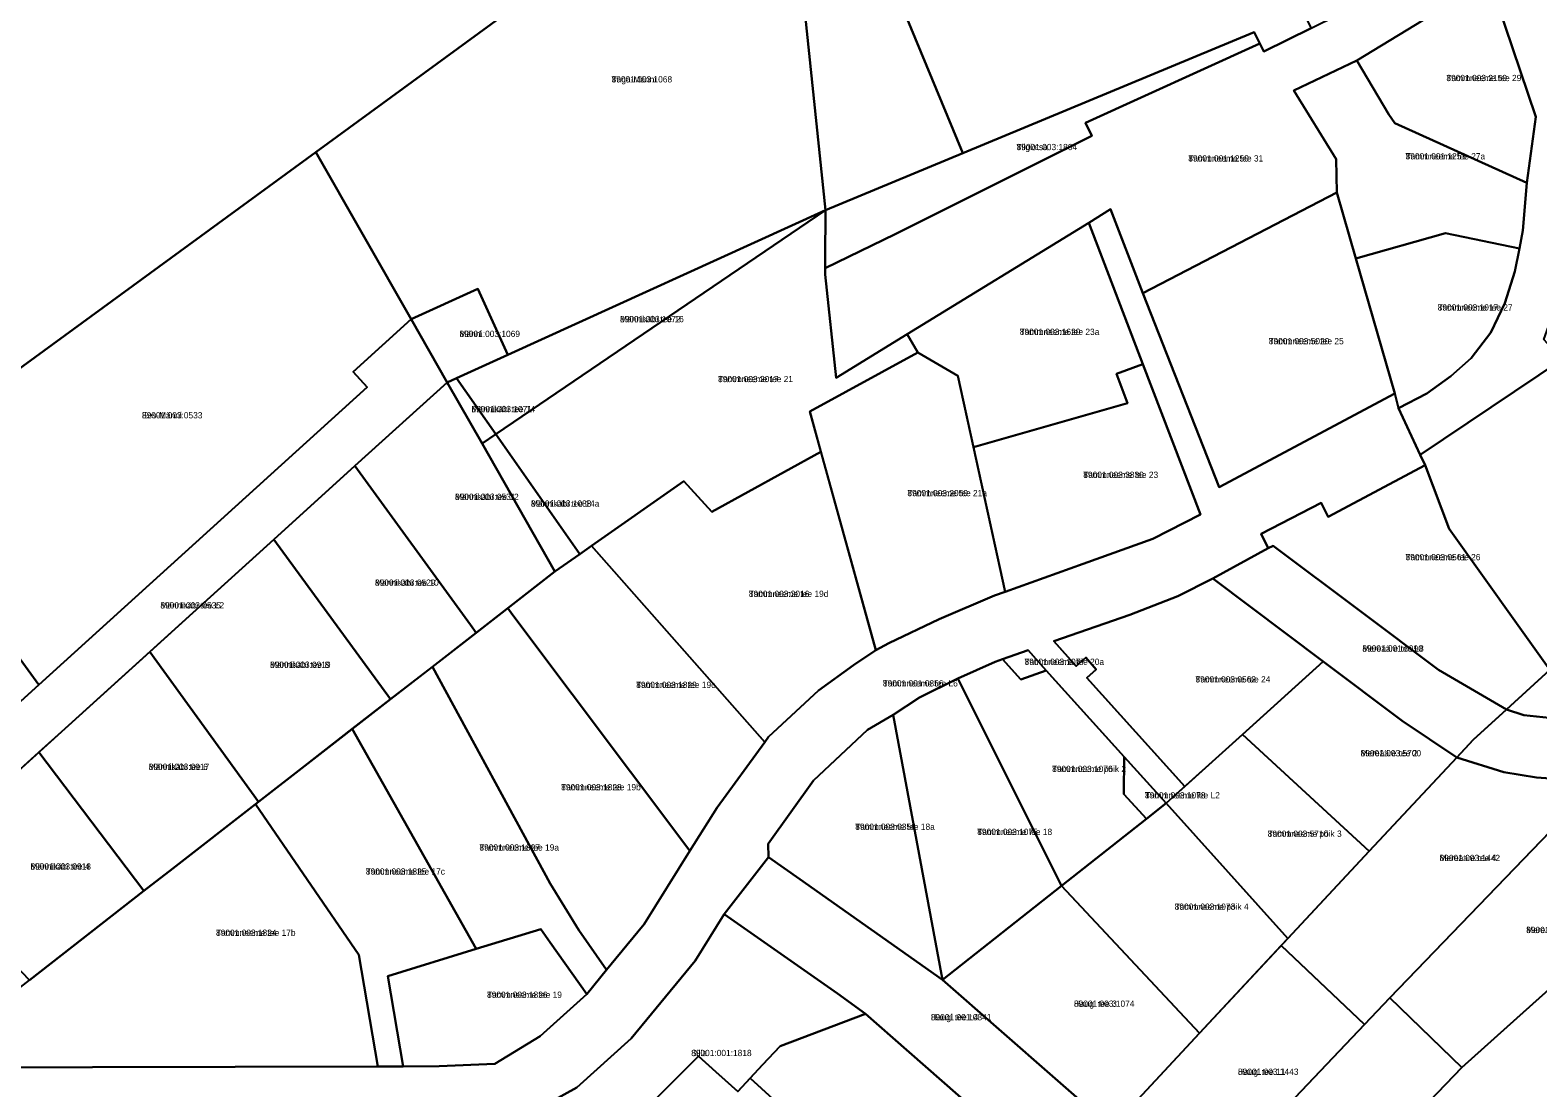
# Model space of a CAD drawing. Extents: x 526849 to 562296, y 6591741 to 6618546.
# Drawn here: x 549963.2 to 550324.5, y 6599418.5 to 6599671.9 of the extents above; entities that cross this region are included whole.
import ezdxf

# ---------------------------------------------------------------- set-up
doc = ezdxf.new("R2010")
doc.units = 0
for name, color, linetype in [('L_AADRESS', 7, 'Continuous'), ('PIIR', 7, 'Continuous'), ('TUNNUS', 7, 'Continuous')]:
    doc.layers.add(name, color=color, linetype=linetype)

msp = doc.modelspace()

# ---------------------------------------------------------------- linework, layer by layer
at = {"layer": 'PIIR'}
for points in [[(550120.44, 6599951.5), (550131.86, 6599957.71), (550132.14, 6599955.03), (550135.52, 6599922.21), (550142.38, 6599855.54), (550143.2, 6599847.59), (550143.81, 6599841.62), (550148.68, 6599794.24), (550154.07, 6599741.82), (550160.25, 6599682.56), (550224.97, 6599706.61), (550249.04, 6599715.69), (550253.16, 6599705.99), (550173, 6599675.56), (550186.76, 6599642.4), (550153.82, 6599628.72), (550143.83, 6599724.58), (550134.04, 6599819.27)], [(550031.61, 6599642.67), (549950.11, 6599583.16), (549916.41, 6599620.77), (549895.32, 6599597.71), (549870.31, 6599624.72), (549877.15, 6599630.15), (549878.36, 6599631.04), (549903.73, 6599650.97), (549961.17, 6599692.9), (549996.94, 6599718.81), (550000, 6599721.04), (550069, 6599771.36), (550116.4, 6599805.93), (550119.7, 6599808.82), (550124.58, 6599812.65), (550134.04, 6599819.27), (550143.83, 6599724.58)], [(550031.61, 6599642.67), (550143.83, 6599724.58), (550153.82, 6599628.72), (550077.68, 6599594.11), (550070.5, 6599609.89), (550054.48, 6599602.6)], [(550186.76, 6599642.4), (550173, 6599675.56), (550253.16, 6599705.99), (550268.85, 6599674.99), (550270.2, 6599672.33), (550258.83, 6599666.72), (550257.88, 6599668.71), (550256.55, 6599671.4)], [(550153.69, 6599613.3), (550153.7, 6599614.84), (550170.52, 6599622.98), (550217.62, 6599646.57), (550216.15, 6599649.66), (550257.88, 6599668.71), (550258.83, 6599666.72), (550270.2, 6599672.33), (550310.36, 6599692.2), (550311.12, 6599689.81), (550312.95, 6599684.03), (550281.15, 6599664.63), (550266.03, 6599657.45), (550276.22, 6599640.99), (550276.37, 6599633), (550229.88, 6599608.87), (550222.15, 6599628.97), (550216.9, 6599625.73), (550173.42, 6599599.06), (550156.38, 6599588.61)], [(550312.95, 6599684.03), (550324.05, 6599651.14), (550321.94, 6599635.28), (550290.28, 6599649.56), (550288.79, 6599651.69), (550281.15, 6599664.63)], [(550153.82, 6599628.72), (550186.76, 6599642.4), (550256.55, 6599671.4), (550257.88, 6599668.71), (550216.15, 6599649.66), (550217.62, 6599646.57), (550170.52, 6599622.98), (550153.7, 6599614.84), (550153.73, 6599616.85)], [(550381.16, 6599658.31), (550390.31, 6599664.95), (550393.25, 6599655.51), (550398.33, 6599645.98), (550405.31, 6599634.63), (550407.66, 6599631.74), (550410.09, 6599627.45), (550417.22, 6599616.57), (550420.09, 6599612.89), (550411.05, 6599603.17), (550379.65, 6599569.41), (550358.23, 6599546.7), (550327.45, 6599518.63), (550303.31, 6599552.43), (550297.52, 6599567.66), (550296.37, 6599570.12), (550330.4, 6599592.99), (550325.98, 6599597.78), (550337.36, 6599629.46), (550359.08, 6599642.63)], [(550276.22, 6599640.99), (550266.03, 6599657.45), (550281.15, 6599664.63), (550288.79, 6599651.69), (550290.28, 6599649.56), (550321.94, 6599635.28), (550320.94, 6599623.9), (550320.15, 6599619.56), (550302.43, 6599623.26), (550280.93, 6599617.17), (550276.37, 6599633)], [(549927.6, 6599566.67), (549940.27, 6599575.96), (549950.11, 6599583.16), (550031.61, 6599642.67), (550054.48, 6599602.6), (550040.58, 6599590.01), (550043.94, 6599586.31), (549965.28, 6599515.05), (549956.54, 6599527.02), (549931.13, 6599561.83)], [(550248.13, 6599562.36), (550229.88, 6599608.87), (550276.37, 6599633), (550280.93, 6599617.17), (550290.24, 6599584.79)], [(550065.39, 6599588.52), (550077.68, 6599594.11), (550153.82, 6599628.72), (550074.8, 6599575.08)], [(550074.8, 6599575.08), (550153.82, 6599628.72), (550153.73, 6599616.85), (550153.7, 6599614.84), (550153.69, 6599613.3), (550156.38, 6599588.61), (550173.42, 6599599.06), (550175.95, 6599594.65), (550150.04, 6599580.48), (550152.71, 6599570.84), (550126.6, 6599556.47), (550119.82, 6599563.82), (550097.7, 6599548.33), (550094.9, 6599546.37)], [(550216.9, 6599625.73), (550229.9, 6599591.87), (550223.55, 6599589.53), (550226.22, 6599582.49), (550189.24, 6599571.99), (550185.49, 6599589.09), (550175.95, 6599594.65), (550173.42, 6599599.06)], [(550280.93, 6599617.17), (550302.43, 6599623.26), (550320.15, 6599619.56), (550319.05, 6599614.06), (550316.66, 6599606.44), (550313.27, 6599599.41), (550308.59, 6599593.28), (550303.7, 6599588.94), (550297.9, 6599584.8), (550291.18, 6599581.28), (550290.24, 6599584.79)], [(550054.48, 6599602.6), (550070.5, 6599609.89), (550077.68, 6599594.11), (550065.39, 6599588.52), (550063.11, 6599587.49)], [(550054.48, 6599602.6), (550063.11, 6599587.49), (550041.02, 6599567.48), (550021.57, 6599549.86), (550002.2, 6599532.31), (549972.37, 6599505.33), (549936.05, 6599472.4), (549927.07, 6599464.06), (549920.65, 6599470.74), (549918.37, 6599472.55), (549965.28, 6599515.05), (550043.94, 6599586.31), (550040.58, 6599590.01)], [(550165.87, 6599523.31), (550150.04, 6599580.48), (550175.95, 6599594.65), (550185.49, 6599589.09), (550196.84, 6599537.32), (550194.34, 6599536.42), (550181.02, 6599530.76), (550168.95, 6599525.04)], [(550226.22, 6599582.49), (550223.55, 6599589.53), (550229.9, 6599591.87), (550243.66, 6599555.84), (550232.24, 6599550.04), (550215.53, 6599544.03), (550196.84, 6599537.32), (550189.24, 6599571.99)], [(550041.02, 6599567.48), (550063.11, 6599587.49), (550071.49, 6599572.83), (550088.97, 6599542.22), (550070.06, 6599527.51), (550068.68, 6599529.39)], [(550063.11, 6599587.49), (550065.39, 6599588.52), (550074.8, 6599575.08), (550071.49, 6599572.83)], [(550071.49, 6599572.83), (550074.8, 6599575.08), (550094.9, 6599546.37), (550088.97, 6599542.22)], [(550097.7, 6599548.33), (550119.82, 6599563.82), (550126.6, 6599556.47), (550152.71, 6599570.84), (550165.87, 6599523.31), (550160.48, 6599519.77), (550152.09, 6599513.67), (550140.18, 6599502.61), (550139.24, 6599501.33)], [(550021.57, 6599549.86), (550041.02, 6599567.48), (550068.68, 6599529.39), (550070.06, 6599527.51), (550061.82, 6599521.11), (550049.52, 6599511.56)], [(550258.2, 6599551.18), (550272.65, 6599558.62), (550274.25, 6599555.29), (550297.52, 6599567.66), (550303.31, 6599552.43), (550327.45, 6599518.63), (550317.07, 6599509.16), (550300.72, 6599518.66), (550282.13, 6599532.63), (550261.07, 6599548.34), (550259.87, 6599547.74)], [(549991.83, 6599522.94), (550002.2, 6599532.31), (550021.57, 6599549.86), (550049.52, 6599511.56), (550028.99, 6599495.61), (550017.92, 6599487.01)], [(550077.64, 6599533.41), (550088.97, 6599542.22), (550094.9, 6599546.37), (550097.7, 6599548.33), (550139.24, 6599501.33), (550127.81, 6599485.67), (550121.31, 6599475.25), (550078.9, 6599531.73)], [(550261.07, 6599548.34), (550282.13, 6599532.63), (550300.72, 6599518.66), (550317.07, 6599509.16), (550309.04, 6599501.84), (550305.11, 6599497.63), (550292.02, 6599506.43), (550273.12, 6599520.64), (550246.64, 6599540.52), (550259.87, 6599547.74)], [(550358.23, 6599546.7), (550372.07, 6599533.58), (550345.41, 6599505.81), (550342.54, 6599506.24), (550328.81, 6599506.97), (550321.2, 6599507.77), (550317.07, 6599509.16), (550327.45, 6599518.63)], [(550208.52, 6599525.48), (550226.76, 6599531.82), (550238.28, 6599536.28), (550246.64, 6599540.52), (550273.12, 6599520.64), (550253.73, 6599503.15), (550239.91, 6599490.68), (550216.41, 6599516.73), (550218.72, 6599518.72), (550216.17, 6599521.59), (550213.87, 6599519.54)], [(550059.58, 6599519.37), (550070.06, 6599527.51), (550077.64, 6599533.41), (550078.9, 6599531.73), (550121.31, 6599475.25), (550110.37, 6599457.72), (550103.58, 6599449.47), (550101.32, 6599446.72), (550094.68, 6599456.23), (550087.84, 6599467.42)], [(549889.88, 6599506.62), (549956.54, 6599527.02), (549965.28, 6599515.05), (549918.37, 6599472.55), (549917.81, 6599473), (549899.21, 6599491.48), (549895.84, 6599490.7)], [(549965.28, 6599498.9), (549972.37, 6599505.33), (549991.83, 6599522.94), (550017.92, 6599487.01), (549997.36, 6599471.02), (549990.45, 6599465.65)], [(550185.5, 6599516.55), (550194.47, 6599520.52), (550196.26, 6599521.15), (550200.61, 6599516.32), (550206.73, 6599518.5), (550225.41, 6599497.79), (550225.3, 6599488.87), (550230.75, 6599482.95), (550210.36, 6599466.85)], [(550196.26, 6599521.15), (550202.4, 6599523.3), (550206.73, 6599518.5), (550200.61, 6599516.32)], [(550284.15, 6599475.18), (550253.73, 6599503.15), (550273.12, 6599520.64), (550292.02, 6599506.43), (550305.11, 6599497.63)], [(550040.39, 6599504.47), (550049.52, 6599511.56), (550059.58, 6599519.37), (550087.84, 6599467.42), (550094.68, 6599456.23), (550101.32, 6599446.72), (550096.58, 6599440.95), (550087.81, 6599453.32), (550085.56, 6599456.5), (550070.11, 6599451.77)], [(550170, 6599507.86), (550176.34, 6599511.96), (550185.5, 6599516.55), (550210.36, 6599466.85), (550181.84, 6599444.34)], [(550150.94, 6599492.13), (550163.88, 6599504.25), (550170, 6599507.86), (550181.84, 6599444.34), (550147.62, 6599468.48), (550140.11, 6599473.76), (550140.03, 6599476.98)], [(550317.07, 6599509.16), (550321.2, 6599507.77), (550328.81, 6599506.97), (550342.54, 6599506.24), (550345.41, 6599505.81), (550351.57, 6599504.9), (550343.47, 6599496.46), (550338.96, 6599491.78), (550324.24, 6599492.81), (550316.42, 6599494.13), (550305.11, 6599497.63), (550309.04, 6599501.84)], [(550017.18, 6599486.43), (550017.92, 6599487.01), (550028.99, 6599495.61), (550040.39, 6599504.47), (550070.11, 6599451.77), (550048.89, 6599445.26), (550052.6, 6599423.6), (550046.52, 6599423.58), (550041.96, 6599450.33)], [(550284.15, 6599475.18), (550264.65, 6599454.29), (550235.45, 6599486.66), (550253.73, 6599503.15)], [(549936.05, 6599472.4), (549965.28, 6599498.9), (549990.45, 6599465.65), (549963.01, 6599444.32)], [(550225.41, 6599497.79), (550235.45, 6599486.66), (550230.75, 6599482.95), (550225.3, 6599488.87)], [(550305.11, 6599497.63), (550316.42, 6599494.13), (550324.24, 6599492.81), (550338.96, 6599491.78), (550336.02, 6599488.73), (550289.09, 6599440.06), (550283, 6599433.66), (550263.02, 6599452.56), (550264.65, 6599454.29), (550284.15, 6599475.18)], [(550336.02, 6599488.73), (550354.4, 6599471.61), (550338.48, 6599453.54), (550333.28, 6599447.47), (550319.47, 6599435.16), (550306.33, 6599423.38), (550289.09, 6599440.06)], [(549943.82, 6599423.37), (549953.27, 6599436.76), (549963.01, 6599444.32), (549990.45, 6599465.65), (549997.36, 6599471.02), (550017.18, 6599486.43), (550041.96, 6599450.33), (550046.52, 6599423.58)], [(550210.36, 6599466.85), (550230.75, 6599482.95), (550235.45, 6599486.66), (550264.65, 6599454.29), (550243.43, 6599431.58)], [(550140.11, 6599473.76), (550147.62, 6599468.48), (550181.84, 6599444.34), (550222.34, 6599408.94), (550209.75, 6599395.56), (550169.96, 6599430.49), (550163.43, 6599436.24), (550156.66, 6599441.08), (550129.55, 6599460.1)], [(550181.84, 6599444.34), (550210.36, 6599466.85), (550243.43, 6599431.58), (550222.34, 6599408.94)], [(550338.48, 6599453.54), (550370.8, 6599421.44), (550391.08, 6599440.74), (550396.22, 6599451.02), (550407.35, 6599463.14), (550412.23, 6599460.02), (550417.73, 6599455.69), (550376.16, 6599416.14), (550359.05, 6599399.06), (550342.91, 6599382.73), (550339.12, 6599378.58), (550318.87, 6599396.92), (550298.56, 6599415.29), (550306.33, 6599423.38), (550319.47, 6599435.16), (550333.28, 6599447.47)], [(550081.31, 6599403.33), (550079.78, 6599410.62), (550094.17, 6599418.58), (550107.25, 6599430.32), (550112.08, 6599436.18), (550122.56, 6599448.95), (550129.55, 6599460.1), (550156.66, 6599441.08), (550163.43, 6599436.24), (550142.97, 6599428.5), (550138.68, 6599423.99), (550135.76, 6599420.79), (550132.8, 6599417.6), (550129.78, 6599420.32), (550127.55, 6599422.3), (550123.34, 6599426.05), (550120.95, 6599423.65), (550089.5, 6599392.07)], [(550052.6, 6599423.6), (550048.89, 6599445.26), (550070.11, 6599451.77), (550085.56, 6599456.5), (550087.81, 6599453.32), (550096.58, 6599440.95), (550085.39, 6599430.83), (550074.54, 6599424.23), (550061.2, 6599423.68)], [(550263.02, 6599452.56), (550283, 6599433.66), (550242.17, 6599390.67), (550222.34, 6599408.94), (550243.43, 6599431.58)], [(550283, 6599433.66), (550289.09, 6599440.06), (550306.33, 6599423.38), (550298.56, 6599415.29), (550259.95, 6599374.33), (550242.17, 6599390.67)], [(550145.7, 6599411.7), (550135.76, 6599420.79), (550138.68, 6599423.99), (550142.97, 6599428.5), (550163.43, 6599436.24), (550169.96, 6599430.49), (550209.75, 6599395.56), (550189.25, 6599373.56)], [(550097.98, 6599380.38), (550089.5, 6599392.07), (550120.95, 6599423.65), (550123.34, 6599426.05), (550127.55, 6599422.3), (550129.78, 6599420.32), (550132.8, 6599417.6), (550135.76, 6599420.79), (550145.7, 6599411.7), (550133, 6599398.11), (550108.1, 6599371.51)]]:
    msp.add_lwpolyline(points, close=True, dxfattribs=at)
for points in [[(550330.4, 6599592.99), (550296.37, 6599570.12), (550291.18, 6599581.28), (550297.9, 6599584.8), (550303.7, 6599588.94), (550308.59, 6599593.28), (550313.27, 6599599.41), (550316.66, 6599606.44), (550319.05, 6599614.06), (550320.15, 6599619.56), (550320.94, 6599623.9), (550321.94, 6599635.28), (550324.05, 6599651.14), (550312.95, 6599684.03)], [(549943.82, 6599423.37), (550046.52, 6599423.58), (550052.6, 6599423.6), (550061.2, 6599423.68), (550074.54, 6599424.23), (550085.39, 6599430.83), (550096.58, 6599440.95), (550101.32, 6599446.72), (550103.58, 6599449.47), (550110.37, 6599457.72), (550121.31, 6599475.25), (550127.81, 6599485.67), (550139.24, 6599501.33), (550140.18, 6599502.61), (550152.09, 6599513.67), (550160.48, 6599519.77), (550165.87, 6599523.31), (550168.95, 6599525.04), (550181.02, 6599530.76), (550194.34, 6599536.42), (550196.84, 6599537.32), (550215.53, 6599544.03), (550232.24, 6599550.04), (550243.66, 6599555.84), (550229.9, 6599591.87), (550216.9, 6599625.73), (550222.15, 6599628.97), (550229.88, 6599608.87), (550248.13, 6599562.36), (550290.24, 6599584.79), (550291.18, 6599581.28), (550296.37, 6599570.12), (550297.52, 6599567.66), (550274.25, 6599555.29), (550272.65, 6599558.62), (550258.2, 6599551.18), (550259.87, 6599547.74), (550246.64, 6599540.52), (550238.28, 6599536.28), (550226.76, 6599531.82), (550208.52, 6599525.48), (550213.87, 6599519.54), (550216.17, 6599521.59), (550218.72, 6599518.72), (550216.41, 6599516.73), (550239.91, 6599490.68), (550235.45, 6599486.66), (550225.41, 6599497.79), (550206.73, 6599518.5), (550202.4, 6599523.3), (550196.26, 6599521.15), (550194.47, 6599520.52), (550185.5, 6599516.55), (550176.34, 6599511.96), (550170, 6599507.86), (550163.88, 6599504.25), (550150.94, 6599492.13), (550140.03, 6599476.98), (550140.11, 6599473.76), (550129.55, 6599460.1), (550122.56, 6599448.95), (550112.08, 6599436.18), (550107.25, 6599430.32), (550094.17, 6599418.58), (550079.78, 6599410.62)]]:
    msp.add_lwpolyline(points, dxfattribs=at)

# ---------------------------------------------------------------- texts
at = {"layer": 'L_AADRESS'}
for s, p in [('Tammneeme tee 29', (550302.63, 6599659.66)), ('Taga-Männi', (550102.54, 6599659.34)), ('Tiigiotsa', (550199.61, 6599643.12)), ('Tammneeme tee 31', (550240.77, 6599640.4)), ('Tammneeme tee 27a', (550292.85, 6599640.9)), ('Männikäbi tee 16', (550104.56, 6599601.9)), ('Tammneeme tee 27', (550300.54, 6599604.7)), ('Männi', (550066.08, 6599598.36)), ('Tammneeme tee 23a', (550200.38, 6599598.86)), ('Tammneeme tee 25', (550260.06, 6599596.62)), ('Tammneeme tee 21', (550128.06, 6599587.54)), ('Männikäbi tee 14', (550068.95, 6599580.35)), ('Ees-Männi', (549989.97, 6599578.86)), ('Tammneeme tee 23', (550215.59, 6599564.6)), ('Männikäbi tee 12', (550065, 6599559.33)), ('Tammneeme tee 21a', (550173.44, 6599560.22)), ('Männikäbi tee 14a', (550083.2, 6599557.71)), ('Tammneeme tee 26', (550292.83, 6599544.88)), ('Männikäbi tee 10', (550045.82, 6599538.76)), ('Männikäbi tee L2', (549994.39, 6599533.33)), ('Tammneeme tee 19d', (550135.43, 6599536.08)), ('Mereääre tee L8', (550282.48, 6599522.99)), ('Männikäbi tee 8', (550020.68, 6599519.1)), ('Tammneeme tee 20a', (550201.51, 6599519.81)), ('Tammneeme tee 24', (550242.48, 6599515.6)), ('Tammneeme tee 19c', (550108.44, 6599514.28)), ('Tammneeme tee L6', (550167.56, 6599514.64)), ('Mereääre tee 2', (550282.06, 6599497.91)), ('Männikäbi tee 6', (549991.6, 6599494.64)), ('Tammneeme põik 2', (550208.12, 6599494.14)), ('Tammneeme tee 19b', (550090.45, 6599489.76)), ('Tammneeme tee L2', (550230.38, 6599487.82)), ('Tammneeme tee 18a', (550160.94, 6599480.29)), ('Tammneeme tee 18', (550190.18, 6599479.06)), ('Tammneeme tee 19a', (550070.86, 6599475.32)), ('Tammneeme põik 3', (550259.8, 6599478.62)), ('Mereääre tee 4', (550300.99, 6599472.81)), ('Männikäbi tee 4', (549963.25, 6599470.78)), ('Tammneeme tee 17c', (550043.64, 6599469.57)), ('Tammneeme põik 4', (550237.5, 6599461.14)), ('Tammneeme tee 17b', (550007.72, 6599454.9)), ('Mereääre tee 6', (550321.75, 6599455.56)), ('Tammneeme tee 19', (550072.68, 6599440.05)), ('Haugi tee 3', (550213.36, 6599437.9)), ('Haugi tee L4', (550179.07, 6599434.66)), ('Silla', (550121.6, 6599426.09)), ('Haugi tee 11', (550252.67, 6599421.6))]:
    msp.add_text(s, height=1.5, dxfattribs=at).set_placement(p)
at = {"layer": 'TUNNUS'}
for s, p in [('89001:003:2150', (550302.63, 6599659.66)), ('89001:003:1068', (550102.54, 6599659.34)), ('89001:003:1804', (550199.61, 6599643.12)), ('89001:001:1250', (550240.77, 6599640.4)), ('89001:001:1251', (550292.85, 6599640.9)), ('89001:003:1072', (550104.56, 6599601.9)), ('89001:003:1017', (550300.54, 6599604.7)), ('89001:003:1069', (550066.08, 6599598.36)), ('89001:003:1620', (550200.38, 6599598.86)), ('89001:003:5020', (550260.06, 6599596.62)), ('89001:003:2017', (550128.06, 6599587.54)), ('89001:003:1071', (550068.95, 6599580.35)), ('89001:003:0533', (549989.97, 6599578.86)), ('89001:003:3830', (550215.59, 6599564.6)), ('89001:003:0531', (550065, 6599559.33)), ('89001:003:2050', (550173.44, 6599560.22)), ('89001:003:1083', (550083.2, 6599557.71)), ('89001:003:0561', (550292.83, 6599544.88)), ('89001:003:0529', (550045.82, 6599538.76)), ('89001:003:0535', (549994.39, 6599533.33)), ('89001:003:2016', (550135.43, 6599536.08)), ('89001:001:0990', (550282.48, 6599522.99)), ('89001:003:0919', (550020.68, 6599519.1)), ('89001:003:1077', (550201.51, 6599519.81)), ('89001:003:0562', (550242.48, 6599515.6)), ('89001:003:1829', (550108.44, 6599514.28)), ('89001:001:0856', (550167.56, 6599514.64)), ('89001:003:5700', (550282.06, 6599497.91)), ('89001:003:0917', (549991.6, 6599494.64)), ('89001:003:1076', (550208.12, 6599494.14)), ('89001:003:1828', (550090.45, 6599489.76)), ('89001:003:1078', (550230.38, 6599487.82)), ('89001:003:0356', (550160.94, 6599480.29)), ('89001:003:1075', (550190.18, 6599479.06)), ('89001:003:1827', (550070.86, 6599475.32)), ('89001:003:5710', (550259.8, 6599478.62)), ('89001:003:1442', (550300.99, 6599472.81)), ('89001:003:0918', (549963.25, 6599470.78)), ('89001:003:1825', (550043.64, 6599469.57)), ('89001:003:1073', (550237.5, 6599461.14)), ('89001:003:1824', (550007.72, 6599454.9)), ('89001:003:4410', (550321.75, 6599455.56)), ('89001:003:1826', (550072.68, 6599440.05)), ('89001:003:1074', (550213.36, 6599437.9)), ('89001:001:0841', (550179.07, 6599434.66)), ('89001:001:1818', (550121.6, 6599426.09)), ('89001:003:1443', (550252.67, 6599421.6))]:
    msp.add_text(s, height=1.5, dxfattribs=at).set_placement(p)

doc.saveas('drawing.dxf')
